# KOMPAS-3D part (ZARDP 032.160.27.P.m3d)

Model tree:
1. Плоскость XY
2. Плоскость ZX
3. Плоскость ZY
4. Ось X
5. Ось Y
6. Ось Z
7. Начало координат
8. Булева операция:1
9. Булева операция:2
10. Булева операция:3
11. Булева операция:4
